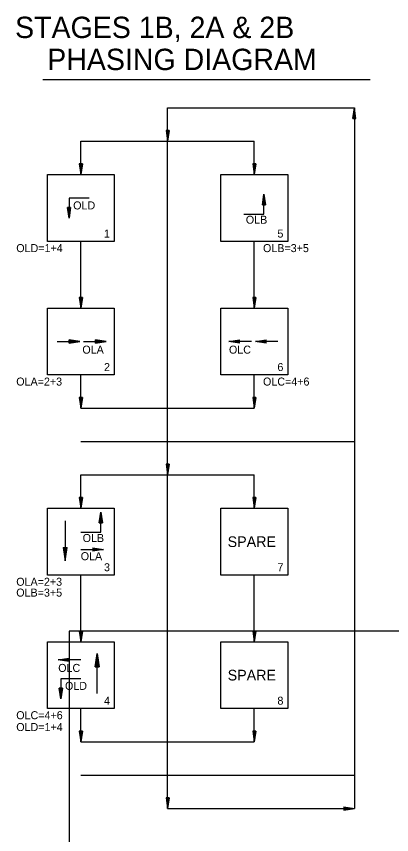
# Model space of a CAD drawing. Extents: x -218554 to 420030, y -566264 to -483460.
# Drawn here: x 418886.5 to 419027.1, y -565587.2 to -565280.7 of the extents above; entities that cross this region are included whole.
import ezdxf

# ---------------------------------------------------------------- set-up
doc = ezdxf.new("R2010")
doc.units = 0
for name, color, linetype in [('R_Draft', 7, 'Continuous'), ('T_Drafting', 7, 'Continuous'), ('T_Notes', 7, 'Continuous'), ('Template', 7, 'Continuous')]:
    doc.layers.add(name, color=color, linetype=linetype)

msp = doc.modelspace()

# ---------------------------------------------------------------- linework, layer by layer
at = {"layer": 'R_Draft'}
for p, q in [((419012.58, -565318.98), (419013.18, -565314.98)), ((419013.78, -565318.98), (419013.18, -565314.98)), ((419012.68, -565318.98), (419013.18, -565315.65)), ((419012.78, -565318.98), (419013.18, -565316.34)), ((419012.88, -565318.98), (419013.18, -565317)), ((419012.99, -565318.98), (419013.18, -565317.68)), ((419013.68, -565318.98), (419013.18, -565315.65)), ((419013.58, -565318.98), (419013.18, -565316.34)), ((419013.48, -565318.98), (419013.18, -565317)), ((419013.38, -565318.98), (419013.18, -565317.68)), ((419012.58, -565318.98), (419013.78, -565318.98)), ((419013.09, -565318.98), (419013.18, -565318.35)), ((419013.28, -565318.98), (419013.18, -565318.35)), ((418942.58, -565323.48), (418943.18, -565327.48)), ((418943.78, -565323.48), (418942.58, -565323.48)), ((418942.68, -565323.48), (418943.18, -565326.81)), ((418942.78, -565323.48), (418943.18, -565326.12)), ((418942.88, -565323.48), (418943.18, -565325.46)), ((418942.99, -565323.48), (418943.18, -565324.78)), ((418943.09, -565323.48), (418943.18, -565324.11)), ((418943.78, -565323.48), (418943.18, -565327.48)), ((418943.38, -565323.48), (418943.18, -565324.78)), ((418943.58, -565323.48), (418943.18, -565326.12)), ((418943.68, -565323.48), (418943.18, -565326.81)), ((418943.48, -565323.48), (418943.18, -565325.46)), ((418943.28, -565323.48), (418943.18, -565324.11)), ((418910.08, -565335.98), (418910.68, -565339.98)), ((418911.28, -565335.98), (418910.08, -565335.98)), ((418910.18, -565335.98), (418910.68, -565339.31)), ((418910.28, -565335.98), (418910.68, -565338.62)), ((418910.38, -565335.98), (418910.68, -565337.96)), ((418910.49, -565335.98), (418910.68, -565337.28)), ((418910.59, -565335.98), (418910.68, -565336.61)), ((418911.28, -565335.98), (418910.68, -565339.98)), ((418910.88, -565335.98), (418910.68, -565337.28)), ((418911.08, -565335.98), (418910.68, -565338.62)), ((418911.18, -565335.98), (418910.68, -565339.31)), ((418910.98, -565335.98), (418910.68, -565337.96)), ((418910.78, -565335.98), (418910.68, -565336.61)), ((418975.08, -565335.98), (418975.68, -565339.98)), ((418976.28, -565335.98), (418975.08, -565335.98)), ((418975.18, -565335.98), (418975.68, -565339.31)), ((418975.28, -565335.98), (418975.68, -565338.62)), ((418975.38, -565335.98), (418975.68, -565337.96)), ((418975.49, -565335.98), (418975.68, -565337.28)), ((418975.59, -565335.98), (418975.68, -565336.61)), ((418976.28, -565335.98), (418975.68, -565339.98)), ((418975.88, -565335.98), (418975.68, -565337.28)), ((418976.08, -565335.98), (418975.68, -565338.62)), ((418976.18, -565335.98), (418975.68, -565339.31)), ((418975.98, -565335.98), (418975.68, -565337.96)), ((418975.78, -565335.98), (418975.68, -565336.61)), ((418910.08, -565385.98), (418910.68, -565389.98)), ((418911.28, -565385.98), (418910.08, -565385.98)), ((418910.18, -565385.98), (418910.68, -565389.31)), ((418910.28, -565385.98), (418910.68, -565388.62)), ((418910.38, -565385.98), (418910.68, -565387.96)), ((418910.49, -565385.98), (418910.68, -565387.28)), ((418910.59, -565385.98), (418910.68, -565386.61)), ((418911.28, -565385.98), (418910.68, -565389.98)), ((418910.88, -565385.98), (418910.68, -565387.28)), ((418911.08, -565385.98), (418910.68, -565388.62)), ((418911.18, -565385.98), (418910.68, -565389.31)), ((418910.98, -565385.98), (418910.68, -565387.96)), ((418910.78, -565385.98), (418910.68, -565386.61)), ((418975.08, -565385.98), (418975.68, -565389.98)), ((418976.28, -565385.98), (418975.08, -565385.98)), ((418975.18, -565385.98), (418975.68, -565389.31)), ((418975.28, -565385.98), (418975.68, -565388.62)), ((418975.38, -565385.98), (418975.68, -565387.96)), ((418975.49, -565385.98), (418975.68, -565387.28)), ((418975.59, -565385.98), (418975.68, -565386.61)), ((418976.28, -565385.98), (418975.68, -565389.98)), ((418975.88, -565385.98), (418975.68, -565387.28)), ((418976.08, -565385.98), (418975.68, -565388.62)), ((418976.18, -565385.98), (418975.68, -565389.31)), ((418975.98, -565385.98), (418975.68, -565387.96)), ((418975.78, -565385.98), (418975.68, -565386.61)), ((418910.08, -565423.48), (418910.68, -565427.48)), ((418911.28, -565423.48), (418910.08, -565423.48)), ((418910.18, -565423.48), (418910.68, -565426.81)), ((418910.28, -565423.48), (418910.68, -565426.12)), ((418910.38, -565423.48), (418910.68, -565425.46)), ((418910.49, -565423.48), (418910.68, -565424.78)), ((418910.59, -565423.48), (418910.68, -565424.11)), ((418911.28, -565423.48), (418910.68, -565427.48)), ((418910.88, -565423.48), (418910.68, -565424.78)), ((418911.08, -565423.48), (418910.68, -565426.12)), ((418911.18, -565423.48), (418910.68, -565426.81)), ((418910.98, -565423.48), (418910.68, -565425.46)), ((418910.78, -565423.48), (418910.68, -565424.11)), ((418975.08, -565423.48), (418975.68, -565427.48)), ((418976.28, -565423.48), (418975.08, -565423.48)), ((418975.18, -565423.48), (418975.68, -565426.81)), ((418975.28, -565423.48), (418975.68, -565426.12)), ((418975.38, -565423.48), (418975.68, -565425.46)), ((418975.49, -565423.48), (418975.68, -565424.78)), ((418975.59, -565423.48), (418975.68, -565424.11)), ((418976.28, -565423.48), (418975.68, -565427.48)), ((418975.88, -565423.48), (418975.68, -565424.78)), ((418976.08, -565423.48), (418975.68, -565426.12)), ((418976.18, -565423.48), (418975.68, -565426.81)), ((418975.98, -565423.48), (418975.68, -565425.46)), ((418975.78, -565423.48), (418975.68, -565424.11)), ((418942.58, -565448.48), (418943.18, -565452.48)), ((418943.78, -565448.48), (418942.58, -565448.48)), ((418942.68, -565448.48), (418943.18, -565451.81)), ((418942.78, -565448.48), (418943.18, -565451.12)), ((418942.88, -565448.48), (418943.18, -565450.46)), ((418942.99, -565448.48), (418943.18, -565449.78)), ((418943.09, -565448.48), (418943.18, -565449.11)), ((418943.78, -565448.48), (418943.18, -565452.48)), ((418943.38, -565448.48), (418943.18, -565449.78)), ((418943.58, -565448.48), (418943.18, -565451.12)), ((418943.68, -565448.48), (418943.18, -565451.81)), ((418943.48, -565448.48), (418943.18, -565450.46)), ((418943.28, -565448.48), (418943.18, -565449.11)), ((418910.08, -565460.98), (418910.68, -565464.98)), ((418911.28, -565460.98), (418910.08, -565460.98)), ((418910.18, -565460.98), (418910.68, -565464.31)), ((418910.28, -565460.98), (418910.68, -565463.62)), ((418910.38, -565460.98), (418910.68, -565462.96)), ((418910.49, -565460.98), (418910.68, -565462.28)), ((418910.59, -565460.98), (418910.68, -565461.61)), ((418911.28, -565460.98), (418910.68, -565464.98)), ((418910.88, -565460.98), (418910.68, -565462.28)), ((418911.08, -565460.98), (418910.68, -565463.62)), ((418911.18, -565460.98), (418910.68, -565464.31)), ((418910.98, -565460.98), (418910.68, -565462.96)), ((418910.78, -565460.98), (418910.68, -565461.61)), ((418975.08, -565460.98), (418975.68, -565464.98)), ((418976.28, -565460.98), (418975.08, -565460.98)), ((418975.18, -565460.98), (418975.68, -565464.31)), ((418975.28, -565460.98), (418975.68, -565463.62)), ((418975.38, -565460.98), (418975.68, -565462.96)), ((418975.49, -565460.98), (418975.68, -565462.28)), ((418975.59, -565460.98), (418975.68, -565461.61)), ((418976.28, -565460.98), (418975.68, -565464.98)), ((418975.88, -565460.98), (418975.68, -565462.28)), ((418976.08, -565460.98), (418975.68, -565463.62)), ((418976.18, -565460.98), (418975.68, -565464.31)), ((418975.98, -565460.98), (418975.68, -565462.96)), ((418975.78, -565460.98), (418975.68, -565461.61)), ((418910.08, -565510.98), (418910.68, -565514.98)), ((418911.28, -565510.98), (418910.08, -565510.98)), ((418910.18, -565510.98), (418910.68, -565514.31)), ((418910.28, -565510.98), (418910.68, -565513.62)), ((418910.38, -565510.98), (418910.68, -565512.96)), ((418910.49, -565510.98), (418910.68, -565512.28)), ((418910.59, -565510.98), (418910.68, -565511.61)), ((418911.28, -565510.98), (418910.68, -565514.98)), ((418910.88, -565510.98), (418910.68, -565512.28)), ((418911.08, -565510.98), (418910.68, -565513.62)), ((418911.18, -565510.98), (418910.68, -565514.31)), ((418910.98, -565510.98), (418910.68, -565512.96)), ((418910.78, -565510.98), (418910.68, -565511.61)), ((418975.08, -565510.98), (418975.68, -565514.98)), ((418976.28, -565510.98), (418975.08, -565510.98)), ((418975.18, -565510.98), (418975.68, -565514.31)), ((418975.28, -565510.98), (418975.68, -565513.62)), ((418975.38, -565510.98), (418975.68, -565512.96)), ((418975.49, -565510.98), (418975.68, -565512.28)), ((418975.59, -565510.98), (418975.68, -565511.61)), ((418976.28, -565510.98), (418975.68, -565514.98)), ((418975.88, -565510.98), (418975.68, -565512.28)), ((418976.08, -565510.98), (418975.68, -565513.62)), ((418976.18, -565510.98), (418975.68, -565514.31)), ((418975.98, -565510.98), (418975.68, -565512.96)), ((418975.78, -565510.98), (418975.68, -565511.61)), ((418910.08, -565548.48), (418910.68, -565552.48)), ((418911.28, -565548.48), (418910.08, -565548.48)), ((418910.18, -565548.48), (418910.68, -565551.81)), ((418910.28, -565548.48), (418910.68, -565551.12)), ((418910.38, -565548.48), (418910.68, -565550.46)), ((418910.49, -565548.48), (418910.68, -565549.78)), ((418910.59, -565548.48), (418910.68, -565549.11)), ((418911.28, -565548.48), (418910.68, -565552.48)), ((418910.88, -565548.48), (418910.68, -565549.78)), ((418911.08, -565548.48), (418910.68, -565551.12)), ((418911.18, -565548.48), (418910.68, -565551.81)), ((418910.98, -565548.48), (418910.68, -565550.46)), ((418910.78, -565548.48), (418910.68, -565549.11)), ((418975.08, -565548.48), (418975.68, -565552.48)), ((418976.28, -565548.48), (418975.08, -565548.48)), ((418975.18, -565548.48), (418975.68, -565551.81)), ((418975.28, -565548.48), (418975.68, -565551.12)), ((418975.38, -565548.48), (418975.68, -565550.46)), ((418975.49, -565548.48), (418975.68, -565549.78)), ((418975.59, -565548.48), (418975.68, -565549.11)), ((418976.28, -565548.48), (418975.68, -565552.48)), ((418975.88, -565548.48), (418975.68, -565549.78)), ((418976.08, -565548.48), (418975.68, -565551.12)), ((418976.18, -565548.48), (418975.68, -565551.81)), ((418975.98, -565548.48), (418975.68, -565550.46)), ((418975.78, -565548.48), (418975.68, -565549.11)), ((418942.58, -565573.48), (418943.18, -565577.48)), ((418943.78, -565573.48), (418942.58, -565573.48)), ((418942.68, -565573.48), (418943.18, -565576.81)), ((418942.78, -565573.48), (418943.18, -565576.12)), ((418942.88, -565573.48), (418943.18, -565575.46)), ((418942.99, -565573.48), (418943.18, -565574.78)), ((418943.09, -565573.48), (418943.18, -565574.11)), ((418943.78, -565573.48), (418943.18, -565577.48)), ((418943.38, -565573.48), (418943.18, -565574.78)), ((418943.58, -565573.48), (418943.18, -565576.12)), ((418943.68, -565573.48), (418943.18, -565576.81)), ((418943.48, -565573.48), (418943.18, -565575.46)), ((418943.28, -565573.48), (418943.18, -565574.11)), ((419009.18, -565576.88), (419013.18, -565577.48)), ((419009.18, -565576.88), (419009.18, -565578.08)), ((419009.18, -565576.98), (419012.51, -565577.48)), ((419009.18, -565577.08), (419011.83, -565577.48)), ((419009.18, -565577.18), (419011.16, -565577.48)), ((419009.18, -565577.29), (419010.48, -565577.48)), ((419009.18, -565577.39), (419009.81, -565577.48)), ((419009.18, -565578.08), (419013.18, -565577.48)), ((419009.18, -565577.68), (419010.48, -565577.48)), ((419009.18, -565577.88), (419011.83, -565577.48)), ((419009.18, -565577.98), (419012.51, -565577.48)), ((419009.18, -565577.78), (419011.16, -565577.48)), ((419009.18, -565577.57), (419009.81, -565577.48))]:
    msp.add_line(p, q, dxfattribs=at)
at = {"layer": 'T_Drafting'}
for p, q in [((418943.18, -565577.48), (418943.18, -565314.98)), ((418943.18, -565314.98), (419013.18, -565314.98)), ((419013.18, -565314.98), (419013.18, -565577.48)), ((418910.68, -565339.98), (418910.68, -565327.48)), ((418910.68, -565327.48), (418975.68, -565327.48)), ((418975.68, -565339.98), (418975.68, -565327.48)), ((418978.68, -565351.29), (418979.28, -565347.29)), ((418979.28, -565347.95), (418978.78, -565351.29)), ((418978.88, -565351.29), (418979.28, -565348.64)), ((418979.28, -565354.79), (418979.28, -565347.29)), ((418979.28, -565347.29), (418979.88, -565351.29)), ((418979.78, -565351.29), (418979.28, -565347.95)), ((418979.28, -565348.64), (418979.68, -565351.29)), ((418913.72, -565348.84), (418906.22, -565348.84)), ((418906.22, -565348.84), (418906.22, -565356.34)), ((418978.68, -565351.29), (418979.88, -565351.29)), ((418979.28, -565349.31), (418978.98, -565351.29)), ((418979.09, -565351.29), (418979.28, -565349.99)), ((418979.28, -565350.65), (418979.19, -565351.29)), ((418979.58, -565351.29), (418979.28, -565349.31)), ((418979.28, -565349.99), (418979.48, -565351.29)), ((418979.38, -565351.29), (418979.28, -565350.65)), ((418906.22, -565356.34), (418905.62, -565352.34)), ((418906.82, -565352.34), (418905.62, -565352.34)), ((418905.72, -565352.34), (418906.22, -565355.67)), ((418906.22, -565354.98), (418905.83, -565352.34)), ((418905.93, -565352.34), (418906.22, -565354.32)), ((418906.22, -565353.64), (418906.03, -565352.34)), ((418906.13, -565352.34), (418906.22, -565352.97)), ((418906.22, -565352.97), (418906.32, -565352.34)), ((418906.42, -565352.34), (418906.22, -565353.64)), ((418906.22, -565354.32), (418906.52, -565352.34)), ((418906.62, -565352.34), (418906.22, -565354.98)), ((418906.22, -565355.67), (418906.72, -565352.34)), ((418906.82, -565352.34), (418906.22, -565356.34)), ((418971.78, -565354.79), (418979.28, -565354.79)), ((418910.68, -565389.98), (418910.68, -565364.98)), ((418975.68, -565389.98), (418975.68, -565364.98)), ((418901.81, -565402.48), (418910.3, -565402.48)), ((418910.3, -565402.48), (418906.3, -565401.88)), ((418906.3, -565403.08), (418906.3, -565401.88)), ((418906.3, -565401.98), (418909.63, -565402.48)), ((418908.94, -565402.48), (418906.3, -565402.08)), ((418906.3, -565402.18), (418908.28, -565402.48)), ((418907.6, -565402.48), (418906.3, -565402.28)), ((418906.3, -565402.39), (418906.93, -565402.48)), ((418906.93, -565402.48), (418906.3, -565402.57)), ((418906.3, -565402.67), (418907.6, -565402.48)), ((418908.28, -565402.48), (418906.3, -565402.78)), ((418906.3, -565402.88), (418908.94, -565402.48)), ((418909.63, -565402.48), (418906.3, -565402.98)), ((418906.3, -565403.08), (418910.3, -565402.48)), ((418911.71, -565402.48), (418920.19, -565402.48)), ((418920.19, -565402.48), (418916.19, -565401.88)), ((418916.19, -565403.08), (418916.19, -565401.88)), ((418916.19, -565401.98), (418919.53, -565402.48)), ((418918.84, -565402.48), (418916.19, -565402.08)), ((418916.19, -565402.18), (418918.17, -565402.48)), ((418917.49, -565402.48), (418916.19, -565402.28)), ((418916.19, -565402.39), (418916.83, -565402.48)), ((418916.83, -565402.48), (418916.19, -565402.57)), ((418916.19, -565402.67), (418917.49, -565402.48)), ((418918.17, -565402.48), (418916.19, -565402.78)), ((418916.19, -565402.88), (418918.84, -565402.48)), ((418919.53, -565402.48), (418916.19, -565402.98)), ((418916.19, -565403.08), (418920.19, -565402.48)), ((418966.17, -565402.48), (418970.17, -565401.88)), ((418974.66, -565402.48), (418966.17, -565402.48)), ((418970.17, -565403.08), (418966.17, -565402.48)), ((418970.17, -565401.98), (418966.84, -565402.48)), ((418966.84, -565402.48), (418970.17, -565402.98)), ((418967.53, -565402.48), (418970.17, -565402.08)), ((418970.17, -565402.88), (418967.53, -565402.48)), ((418970.17, -565402.18), (418968.19, -565402.48)), ((418968.19, -565402.48), (418970.17, -565402.78)), ((418968.87, -565402.48), (418970.17, -565402.28)), ((418970.17, -565402.67), (418968.87, -565402.48)), ((418970.17, -565402.39), (418969.54, -565402.48)), ((418969.54, -565402.48), (418970.17, -565402.57)), ((418970.17, -565403.08), (418970.17, -565401.88)), ((418976.07, -565402.48), (418980.07, -565401.88)), ((418984.55, -565402.48), (418976.07, -565402.48)), ((418980.07, -565403.08), (418976.07, -565402.48)), ((418980.07, -565401.98), (418976.73, -565402.48)), ((418976.73, -565402.48), (418980.07, -565402.98)), ((418977.42, -565402.48), (418980.07, -565402.08)), ((418980.07, -565402.88), (418977.42, -565402.48)), ((418980.07, -565402.18), (418978.09, -565402.48)), ((418978.09, -565402.48), (418980.07, -565402.78)), ((418978.77, -565402.48), (418980.07, -565402.28)), ((418980.07, -565402.67), (418978.77, -565402.48)), ((418980.07, -565402.39), (418979.43, -565402.48)), ((418979.43, -565402.48), (418980.07, -565402.57)), ((418980.07, -565403.08), (418980.07, -565401.88)), ((418910.68, -565427.48), (418910.68, -565414.98)), ((418975.68, -565427.48), (418975.68, -565414.98)), ((418910.68, -565427.48), (418975.68, -565427.48)), ((418910.68, -565439.98), (419013.18, -565439.98)), ((418910.68, -565452.48), (418975.68, -565452.48)), ((418910.68, -565464.98), (418910.68, -565452.48)), ((418975.68, -565464.98), (418975.68, -565452.48)), ((418917.52, -565470.48), (418918.12, -565466.48)), ((418918.12, -565467.15), (418917.62, -565470.48)), ((418917.72, -565470.48), (418918.12, -565467.83)), ((418918.12, -565473.98), (418918.12, -565466.48)), ((418918.12, -565466.48), (418918.72, -565470.48)), ((418918.62, -565470.48), (418918.12, -565467.15)), ((418918.12, -565467.83), (418918.52, -565470.48)), ((418904.84, -565469.7), (418904.84, -565484.7)), ((418917.52, -565470.48), (418918.72, -565470.48)), ((418918.12, -565468.5), (418917.82, -565470.48)), ((418917.93, -565470.48), (418918.12, -565469.18)), ((418918.12, -565469.85), (418918.03, -565470.48)), ((418918.42, -565470.48), (418918.12, -565468.5)), ((418918.12, -565469.18), (418918.32, -565470.48)), ((418918.22, -565470.48), (418918.12, -565469.85)), ((418910.62, -565473.98), (418918.12, -565473.98)), ((418904.09, -565479.7), (418904.84, -565484.7)), ((418904.09, -565479.7), (418905.59, -565479.7)), ((418904.84, -565483.87), (418904.21, -565479.7)), ((418904.34, -565479.7), (418904.84, -565483.01)), ((418904.84, -565482.18), (418904.46, -565479.7)), ((418904.59, -565479.7), (418904.84, -565481.33)), ((418904.84, -565480.49), (418904.72, -565479.7)), ((418904.84, -565484.7), (418905.59, -565479.7)), ((418905.46, -565479.7), (418904.84, -565483.87)), ((418904.84, -565483.01), (418905.33, -565479.7)), ((418905.21, -565479.7), (418904.84, -565482.18)), ((418904.84, -565481.33), (418905.08, -565479.7)), ((418904.95, -565479.7), (418904.84, -565480.49)), ((418910.62, -565480.41), (418919.11, -565480.41)), ((418915.11, -565479.81), (418919.11, -565480.41)), ((418915.11, -565479.81), (418915.11, -565481.01)), ((418918.44, -565480.41), (418915.11, -565479.91)), ((418915.11, -565480.01), (418917.76, -565480.41)), ((418917.09, -565480.41), (418915.11, -565480.11)), ((418915.11, -565480.21), (418916.41, -565480.41)), ((418915.74, -565480.41), (418915.11, -565480.31)), ((418919.11, -565480.41), (418915.11, -565481.01)), ((418915.11, -565480.91), (418918.44, -565480.41)), ((418917.76, -565480.41), (418915.11, -565480.8)), ((418915.11, -565480.7), (418917.09, -565480.41)), ((418916.41, -565480.41), (418915.11, -565480.6)), ((418915.11, -565480.5), (418915.74, -565480.41)), ((418910.68, -565514.98), (418910.68, -565489.98)), ((418975.68, -565514.98), (418975.68, -565489.98)), ((418916.04, -565524.34), (418916.79, -565519.34)), ((418916.79, -565520.17), (418916.16, -565524.34)), ((418916.79, -565534.34), (418916.79, -565519.34)), ((418916.79, -565519.34), (418917.54, -565524.34)), ((418917.41, -565524.34), (418916.79, -565520.17)), ((418902.18, -565521.72), (418906.18, -565521.12)), ((418910.67, -565521.72), (418902.18, -565521.72)), ((418906.18, -565522.32), (418902.18, -565521.72)), ((418906.18, -565521.22), (418902.85, -565521.72)), ((418902.85, -565521.72), (418906.18, -565522.22)), ((418903.53, -565521.72), (418906.18, -565521.32)), ((418906.18, -565522.12), (418903.53, -565521.72)), ((418906.18, -565521.42), (418904.2, -565521.72)), ((418904.2, -565521.72), (418906.18, -565522.02)), ((418904.88, -565521.72), (418906.18, -565521.52)), ((418906.18, -565521.91), (418904.88, -565521.72)), ((418906.18, -565521.62), (418905.55, -565521.72)), ((418905.55, -565521.72), (418906.18, -565521.81)), ((418906.18, -565522.32), (418906.18, -565521.12)), ((418916.29, -565524.34), (418916.79, -565521.03)), ((418916.79, -565521.86), (418916.42, -565524.34)), ((418916.55, -565524.34), (418916.79, -565522.71)), ((418916.79, -565523.55), (418916.67, -565524.34)), ((418916.79, -565521.03), (418917.29, -565524.34)), ((418917.16, -565524.34), (418916.79, -565521.86)), ((418916.79, -565522.71), (418917.03, -565524.34)), ((418916.91, -565524.34), (418916.79, -565523.55)), ((418916.04, -565524.34), (418917.54, -565524.34)), ((418910.67, -565528.84), (418903.17, -565528.84)), ((418903.17, -565528.84), (418903.17, -565536.34)), ((418903.17, -565536.34), (418902.57, -565532.34)), ((418903.77, -565532.34), (418902.57, -565532.34)), ((418902.67, -565532.34), (418903.17, -565535.67)), ((418903.17, -565534.98), (418902.77, -565532.34)), ((418902.87, -565532.34), (418903.17, -565534.32)), ((418903.17, -565533.64), (418902.97, -565532.34)), ((418903.07, -565532.34), (418903.17, -565532.97)), ((418903.17, -565532.97), (418903.26, -565532.34)), ((418903.36, -565532.34), (418903.17, -565533.64)), ((418903.17, -565534.32), (418903.46, -565532.34)), ((418903.56, -565532.34), (418903.17, -565534.98)), ((418903.17, -565535.67), (418903.67, -565532.34)), ((418903.77, -565532.34), (418903.17, -565536.34)), ((418910.68, -565552.48), (418910.68, -565539.98)), ((418975.68, -565552.48), (418975.68, -565539.98)), ((418910.68, -565552.48), (418975.68, -565552.48)), ((418910.68, -565564.98), (419013.18, -565564.98)), ((418943.18, -565577.48), (419013.18, -565577.48))]:
    msp.add_line(p, q, dxfattribs=at)
for points in [[(418898.18, -565339.98), (418923.18, -565339.98), (418923.18, -565364.98), (418898.18, -565364.98)], [(418963.18, -565339.98), (418988.18, -565339.98), (418988.18, -565364.98), (418963.18, -565364.98)], [(418898.18, -565389.98), (418923.18, -565389.98), (418923.18, -565414.98), (418898.18, -565414.98)], [(418963.18, -565389.98), (418988.18, -565389.98), (418988.18, -565414.98), (418963.18, -565414.98)], [(418898.18, -565464.98), (418923.18, -565464.98), (418923.18, -565489.98), (418898.18, -565489.98)], [(418963.18, -565464.98), (418988.18, -565464.98), (418988.18, -565489.98), (418963.18, -565489.98)], [(418898.18, -565514.98), (418923.18, -565514.98), (418923.18, -565539.98), (418898.18, -565539.98)], [(418963.18, -565514.98), (418988.18, -565514.98), (418988.18, -565539.98), (418963.18, -565539.98)]]:
    msp.add_lwpolyline(points, close=True, dxfattribs=at)
at = {"layer": 'T_Notes'}
msp.add_line((418896.46, -565304.27), (419019.1, -565304.27), dxfattribs=at)
at = {"layer": 'Template'}
msp.add_lwpolyline([(419214.2, -565511.02), (418906.32, -565511.02), (418906.32, -565641.34), (419214.2, -565641.34)], close=True, dxfattribs=at)

# ---------------------------------------------------------------- texts
at = {"layer": 'T_Drafting'}
for s, rotation, p in [('OLD', 360, (418907.78, -565353)), ('OLA', 0, (418911.23, -565407.04)), ('OLD', 360, (418904.72, -565533))]:
    msp.add_text(s, height=3, rotation=rotation, dxfattribs=at).set_placement(p)
for s, height, p in [('OLB', 3, (418972.5, -565358.36)), ('OLD=1+4', 3, (418886.45, -565369)), ('OLB=3+5', 3, (418978.94, -565369)), ('OLC', 3, (418966.17, -565407.04)), ('OLA=2+3', 3, (418886.45, -565419)), ('OLC=4+6', 3, (418978.94, -565419)), ('OLB', 3, (418911.34, -565477.61)), ('SPARE', 4, (418965.68, -565479.48)), ('OLA', 3, (418910.62, -565484.43)), ('OLA=2+3', 3, (418886.45, -565494)), ('OLB=3+5', 3, (418886.45, -565498.06)), ('OLC', 3, (418902.18, -565526.28)), ('SPARE', 4, (418965.68, -565529.48)), ('OLC=4+6', 3, (418886.45, -565544)), ('OLD=1+4', 3, (418886.45, -565548.43))]:
    msp.add_text(s, height=height, dxfattribs=at).set_placement(p)
at = {"layer": 'T_Notes'}
for s, p in [('STAGES 1B, 2A & 2B', (418886, -565288.8)), ('PHASING DIAGRAM', (418898.05, -565300.8))]:
    msp.add_text(s, height=8, rotation=360, dxfattribs=at).set_placement(p)
for s, p in [('1', (418919.34, -565363.56)), ('5', (418984.34, -565363.56)), ('2', (418919.34, -565413.56)), ('6', (418984.34, -565413.56)), ('3', (418919.34, -565488.56)), ('7', (418984.34, -565488.56)), ('4', (418919.34, -565538.56)), ('8', (418984.34, -565538.56))]:
    msp.add_text(s, height=3, dxfattribs=at).set_placement(p)

doc.saveas('drawing.dxf')
